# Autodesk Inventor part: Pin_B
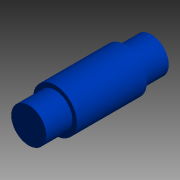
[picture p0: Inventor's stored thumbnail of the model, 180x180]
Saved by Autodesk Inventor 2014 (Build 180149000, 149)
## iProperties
Shininess: 0.0
Length Units: 11272
Angle Units: 11279
Time Units: 11290
Mass Units: 11283
Length Display Precision: 3
Angle Display Precision: 1
Compacted: True
Created: 1999-07
Part Number: Pin_B
Document SubType Name: Modeling
Designer: Administrator
Density: 7.86 g/cm^3
Material: Steel, Mild
Mass: 7.31047 g
Surface Area: 6.05674 cm^2
Volume: 0.930085 cm^3
Appearance: Blue - Semi Gloss
Density: 0.0
Volumn: 0.0
Area: 0.0
PropertySet Name: Model Information
Control State: 0
Master: False
Checked Out: False
Author: Administrator
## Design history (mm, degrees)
node "y-z Plane"
  node "x-z Plane"
  node "x-y Plane"
node "Extrusion1" dims "d0" = 4.7625, "d1" = 0
  sketch "Sketch1"
    geometry: C1 r 3.175 at (0, 0); 1 further point
    constraints: 1 centre point, 1 coincident
    dimensions: "d7" = 6.35 diameter of C1
node "Extrusion2" dims "d3" = 12.7, "d4" = 0
  sketch "Sketch2"
    geometry: C1 r 3.175 at (0, 0) reference; C2 r 3.969 at (0, 0)
    constraints: 1 centre point, 1 coincident
    dimensions: "d2" = 7.9375 diameter of C2
node "Extrusion3" dims "d5" = 4.7625, "d6" = 0
  sketch "Sketch3"
    geometry: C1 r 3.175 at (0, 0) reference
body "Solid1"
